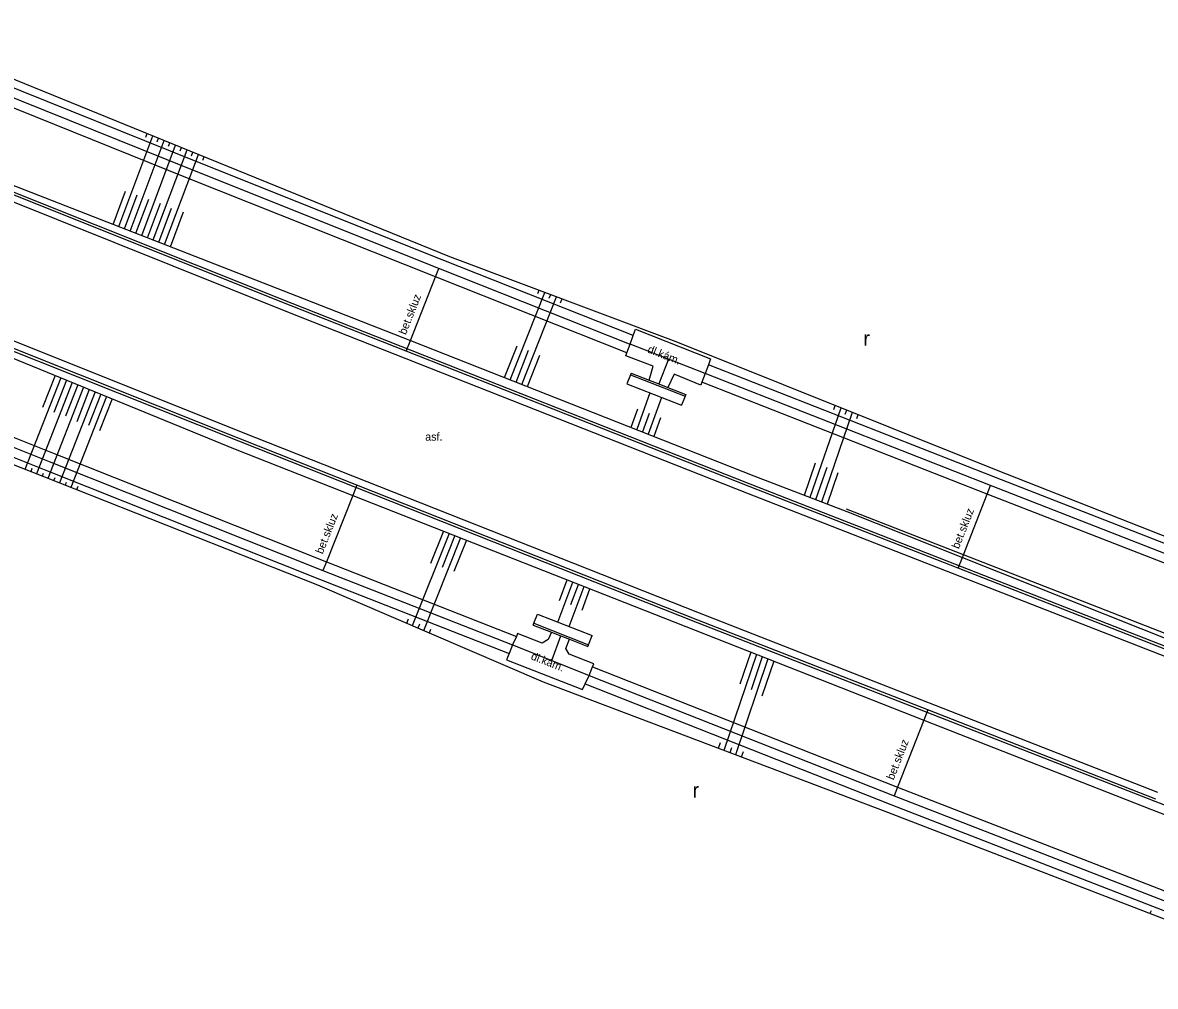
# Model space of a CAD drawing. Extents: x -541281 to -539153, y -1183881 to -1182141.
# Drawn here: x -539618 to -539526, y -1182393.9 to -1182315.6 of the extents above; entities that cross this region are included whole.
import ezdxf

# ---------------------------------------------------------------- set-up
doc = ezdxf.new("R2010")
doc.units = 0
for name, color, linetype in [('Vrstva 10', 7, 'Continuous'), ('Vrstva 11', 7, 'Continuous'), ('Vrstva 14', 7, 'Continuous'), ('Vrstva 15', 7, 'Continuous'), ('Vrstva 36', 7, 'Continuous'), ('Vrstva 40', 7, 'Continuous'), ('Vrstva 7', 7, 'Continuous'), ('Vrstva 9', 7, 'Continuous')]:
    doc.layers.add(name, color=color, linetype=linetype)

msp = doc.modelspace()

# ---------------------------------------------------------------- linework, layer by layer
at = {"layer": 'Vrstva 10'}
for p, q in [((-539633.427, -1182324.268), (-539596.388, -1182339.094)), ((-539600.28, -1182348.833), (-539637.384, -1182333.994)), ((-539596.388, -1182339.094), (-539559.233, -1182353.771)), ((-539563.059, -1182363.539), (-539600.28, -1182348.833)), ((-539559.233, -1182353.771), (-539521.885, -1182368.358)), ((-539525.827, -1182378.1), (-539563.059, -1182363.539))]:
    msp.add_line(p, q, dxfattribs=at)
at = {"layer": 'Vrstva 11'}
for p, q in [((-539604.094, -1182326.792), (-539630.271, -1182316.259)), ((-539604.652, -1182328.184), (-539630.831, -1182317.651)), ((-539596.224, -1182338.56), (-539633.235, -1182323.796)), ((-539583.961, -1182334.823), (-539604.094, -1182326.792)), ((-539584.515, -1182336.217), (-539604.652, -1182328.184)), ((-539600.45, -1182349.35), (-539637.358, -1182334.621)), ((-539568.449, -1182340.984), (-539583.961, -1182334.823)), ((-539568.956, -1182342.397), (-539584.515, -1182336.217)), ((-539639.779, -1182340.846), (-539615.478, -1182350.572)), ((-539568.264, -1182340.47), (-539562.157, -1182342.878)), ((-539640.341, -1182342.238), (-539616.034, -1182351.966)), ((-539566.839, -1182343.459), (-539569.035, -1182342.617)), ((-539567.157, -1182344.596), (-539566.839, -1182343.459)), ((-539539.148, -1182352.463), (-539562.338, -1182343.354)), ((-539568.668, -1182344.166), (-539564.239, -1182345.9)), ((-539565.113, -1182344.124), (-539565.638, -1182345.191)), ((-539562.967, -1182345.004), (-539565.113, -1182344.124)), ((-539539.696, -1182353.859), (-539562.872, -1182344.756)), ((-539568.959, -1182344.911), (-539564.53, -1182346.645)), ((-539615.478, -1182350.572), (-539593.375, -1182359.368)), ((-539616.034, -1182351.966), (-539593.927, -1182360.762)), ((-539515.774, -1182361.592), (-539539.148, -1182352.463)), ((-539516.318, -1182362.99), (-539539.696, -1182353.859)), ((-539593.375, -1182359.368), (-539577.943, -1182365.438)), ((-539593.927, -1182360.762), (-539578.528, -1182366.821)), ((-539576.22, -1182363.616), (-539571.792, -1182365.355)), ((-539576.512, -1182364.36), (-539572.084, -1182366.099)), ((-539575.853, -1182365.977), (-539577.837, -1182365.187)), ((-539575.355, -1182365.683), (-539575.853, -1182365.977)), ((-539575.08, -1182365.084), (-539575.355, -1182365.683)), ((-539573.92, -1182366.403), (-539573.631, -1182365.653)), ((-539573.649, -1182366.862), (-539573.92, -1182366.403)), ((-539571.636, -1182367.641), (-539573.649, -1182366.862)), ((-539578.739, -1182367.321), (-539572.562, -1182369.748)), ((-539571.751, -1182367.902), (-539546.971, -1182377.688)), ((-539572.355, -1182369.277), (-539547.519, -1182379.084)), ((-539546.971, -1182377.688), (-539522.336, -1182387.256)), ((-539547.519, -1182379.084), (-539522.88, -1182388.654))]:
    msp.add_line(p, q, dxfattribs=at)
for points in [[(-539559.033, -1182353.235), (-539586.891, -1182342.243), (-539596.224, -1182338.56)], [(-539569.035, -1182342.617), (-539568.956, -1182342.397), (-539568.702, -1182341.69), (-539568.449, -1182340.984), (-539568.264, -1182340.47)], [(-539562.157, -1182342.878), (-539562.338, -1182343.354), (-539562.605, -1182344.055), (-539562.872, -1182344.756), (-539562.967, -1182345.004)], [(-539568.613, -1182344.026), (-539568.668, -1182344.166), (-539568.959, -1182344.911)], [(-539568.613, -1182344.026), (-539567.157, -1182344.596), (-539566.363, -1182344.907), (-539565.638, -1182345.191), (-539564.184, -1182345.76)], [(-539564.184, -1182345.76), (-539564.239, -1182345.9), (-539564.53, -1182346.645)], [(-539563.193, -1182364.108), (-539590.904, -1182353.131), (-539600.45, -1182349.35)], [(-539521.662, -1182367.863), (-539542.053, -1182359.881), (-539559.033, -1182353.235)], [(-539576.567, -1182364.5), (-539576.512, -1182364.36), (-539576.22, -1182363.616)], [(-539525.991, -1182378.637), (-539544.517, -1182371.402), (-539563.193, -1182364.108)], [(-539576.567, -1182364.5), (-539575.08, -1182365.084), (-539574.331, -1182365.378), (-539573.631, -1182365.653), (-539572.139, -1182366.239)], [(-539577.837, -1182365.187), (-539577.943, -1182365.438), (-539578.255, -1182366.122), (-539578.528, -1182366.821), (-539578.739, -1182367.321)], [(-539572.139, -1182366.239), (-539572.084, -1182366.099), (-539571.792, -1182365.355)], [(-539572.562, -1182369.748), (-539572.355, -1182369.277), (-539572.031, -1182368.598), (-539571.751, -1182367.902), (-539571.636, -1182367.641)]]:
    msp.add_lwpolyline(points, dxfattribs=at)
at = {"layer": 'Vrstva 14'}
for p, q in [((-539630.009, -1182315.556), (-539603.743, -1182326.276)), ((-539604.373, -1182327.488), (-539630.551, -1182316.955)), ((-539633.049, -1182323.249), (-539595.808, -1182337.745)), ((-539603.743, -1182326.276), (-539583.363, -1182334.559)), ((-539584.238, -1182335.52), (-539604.373, -1182327.488)), ((-539583.363, -1182334.559), (-539564.975, -1182341.474)), ((-539637.577, -1182335.183), (-539600.773, -1182350.201)), ((-539584.515, -1182336.217), (-539584.238, -1182335.52)), ((-539568.747, -1182341.673), (-539584.238, -1182335.52)), ((-539586.553, -1182341.386), (-539584.515, -1182336.217)), ((-539640.06, -1182341.542), (-539615.756, -1182351.269)), ((-539586.891, -1182342.243), (-539586.553, -1182341.386)), ((-539568.702, -1182341.69), (-539568.747, -1182341.673)), ((-539565.579, -1182342.894), (-539568.702, -1182341.69)), ((-539564.975, -1182341.474), (-539538.976, -1182351.889)), ((-539616.254, -1182352.488), (-539640.7, -1182342.904)), ((-539565.579, -1182342.894), (-539566.363, -1182344.907)), ((-539562.605, -1182344.055), (-539565.579, -1182342.894)), ((-539562.59, -1182344.061), (-539562.605, -1182344.055)), ((-539539.422, -1182353.161), (-539562.59, -1182344.061)), ((-539615.756, -1182351.269), (-539593.651, -1182360.065)), ((-539538.976, -1182351.889), (-539515.654, -1182361.073)), ((-539594.083, -1182361.274), (-539616.254, -1182352.488)), ((-539558.645, -1182352.367), (-539551.084, -1182355.266)), ((-539590.904, -1182353.131), (-539591.233, -1182353.963)), ((-539516.046, -1182362.291), (-539539.422, -1182353.161)), ((-539542.053, -1182359.881), (-539541.708, -1182359.001)), ((-539541.708, -1182359.001), (-539541.625, -1182358.787)), ((-539593.651, -1182360.065), (-539578.255, -1182366.122)), ((-539575.749, -1182369.148), (-539594.083, -1182361.274)), ((-539575.063, -1182367.378), (-539574.331, -1182365.378)), ((-539578.255, -1182366.122), (-539575.063, -1182367.378)), ((-539575.063, -1182367.378), (-539572.031, -1182368.598)), ((-539572.031, -1182368.598), (-539547.245, -1182378.386)), ((-539547.775, -1182379.728), (-539575.749, -1182369.148)), ((-539544.517, -1182371.402), (-539544.842, -1182372.234)), ((-539544.842, -1182372.234), (-539546.971, -1182377.688)), ((-539546.971, -1182377.688), (-539547.245, -1182378.386)), ((-539547.245, -1182378.386), (-539522.608, -1182387.955)), ((-539523.159, -1182389.228), (-539547.775, -1182379.728))]:
    msp.add_line(p, q, dxfattribs=at)
for points in [[(-539595.808, -1182337.745), (-539586.553, -1182341.386), (-539558.645, -1182352.367)], [(-539600.773, -1182350.201), (-539591.233, -1182353.963), (-539563.423, -1182364.931)], [(-539591.233, -1182353.963), (-539593.375, -1182359.368), (-539593.651, -1182360.065)], [(-539541.625, -1182358.787), (-539539.696, -1182353.859), (-539539.422, -1182353.161)], [(-539551.084, -1182355.266), (-539541.708, -1182359.001), (-539521.503, -1182367.05)], [(-539563.423, -1182364.931), (-539544.842, -1182372.234), (-539526.355, -1182379.501)], [(-539526.355, -1182379.501), (-539498.228, -1182390.3), (-539488.959, -1182393.859)]]:
    msp.add_lwpolyline(points, dxfattribs=at)
at = {"layer": 'Vrstva 15'}
for p, q in [((-539610.243, -1182332.126), (-539607.473, -1182324.754)), ((-539609.311, -1182332.489), (-539606.547, -1182325.132)), ((-539608.05, -1182324.869), (-539607.936, -1182324.565)), ((-539607.118, -1182325.23), (-539607.01, -1182324.943)), ((-539606.19, -1182325.603), (-539606.084, -1182325.321)), ((-539608.379, -1182332.852), (-539605.62, -1182325.51)), ((-539607.447, -1182333.215), (-539604.694, -1182325.888)), ((-539606.515, -1182333.577), (-539603.768, -1182326.266)), ((-539605.261, -1182325.976), (-539605.157, -1182325.699)), ((-539604.343, -1182326.375), (-539604.231, -1182326.077)), ((-539603.405, -1182326.72), (-539603.305, -1182326.454)), ((-539610.709, -1182331.945), (-539609.695, -1182329.247)), ((-539609.777, -1182332.308), (-539608.736, -1182329.538)), ((-539608.845, -1182332.67), (-539607.805, -1182329.902)), ((-539607.913, -1182333.033), (-539606.857, -1182330.222)), ((-539606.981, -1182333.396), (-539605.944, -1182330.636)), ((-539606.049, -1182333.759), (-539604.981, -1182330.915)), ((-539576.197, -1182337.567), (-539576.089, -1182337.295)), ((-539578.435, -1182344.581), (-539575.62, -1182337.471)), ((-539577.504, -1182344.947), (-539574.684, -1182337.823)), ((-539575.267, -1182337.937), (-539575.152, -1182337.647)), ((-539574.347, -1182338.33), (-539574.216, -1182337.999)), ((-539578.9, -1182344.398), (-539577.875, -1182341.808)), ((-539577.969, -1182344.764), (-539576.943, -1182342.173)), ((-539577.039, -1182345.13), (-539576.032, -1182342.587)), ((-539614.95, -1182344.416), (-539617.859, -1182351.859)), ((-539615.412, -1182344.228), (-539616.429, -1182346.83)), ((-539614.486, -1182344.605), (-539615.511, -1182347.228)), ((-539614.023, -1182344.794), (-539616.927, -1182352.224)), ((-539613.098, -1182345.172), (-539615.997, -1182352.59)), ((-539612.172, -1182345.55), (-539615.067, -1182352.958)), ((-539613.561, -1182344.983), (-539614.56, -1182347.54)), ((-539612.634, -1182345.361), (-539613.66, -1182347.987)), ((-539567.085, -1182345.645), (-539568.165, -1182348.621)), ((-539611.245, -1182345.928), (-539614.137, -1182353.327)), ((-539611.709, -1182345.739), (-539612.703, -1182348.283)), ((-539610.782, -1182346.117), (-539611.802, -1182348.728)), ((-539566.153, -1182346.009), (-539567.234, -1182348.988)), ((-539568.091, -1182346.949), (-539568.631, -1182348.438)), ((-539567.163, -1182347.324), (-539567.7, -1182348.804)), ((-539554.067, -1182354.122), (-539551.567, -1182346.845)), ((-539553.133, -1182354.48), (-539550.638, -1182347.217)), ((-539552.14, -1182346.975), (-539552.032, -1182346.659)), ((-539551.22, -1182347.374), (-539551.102, -1182347.031)), ((-539550.284, -1182347.73), (-539550.172, -1182347.404)), ((-539566.219, -1182347.654), (-539566.769, -1182349.171)), ((-539617.293, -1182351.788), (-539617.392, -1182352.042)), ((-539554.534, -1182353.943), (-539553.633, -1182351.321)), ((-539553.6, -1182354.301), (-539552.699, -1182351.679)), ((-539552.665, -1182354.66), (-539551.787, -1182352.105)), ((-539616.38, -1182352.197), (-539616.462, -1182352.406)), ((-539615.435, -1182352.529), (-539615.531, -1182352.774)), ((-539614.513, -1182352.916), (-539614.602, -1182353.143)), ((-539613.567, -1182353.241), (-539613.672, -1182353.511)), ((-539583.398, -1182357.053), (-539586.407, -1182364.57)), ((-539582.468, -1182357.42), (-539585.488, -1182364.965)), ((-539583.863, -1182356.87), (-539584.919, -1182359.508)), ((-539582.933, -1182357.237), (-539583.965, -1182359.814)), ((-539582.003, -1182357.604), (-539583.022, -1182360.15)), ((-539574.57, -1182364.264), (-539573.359, -1182361.012)), ((-539574.448, -1182362.505), (-539573.824, -1182360.829)), ((-539573.504, -1182362.836), (-539572.894, -1182361.196)), ((-539573.638, -1182364.63), (-539572.428, -1182361.379)), ((-539572.608, -1182363.296), (-539571.963, -1182361.563)), ((-539586.729, -1182364.029), (-539586.867, -1182364.373)), ((-539585.813, -1182364.431), (-539585.948, -1182364.768)), ((-539584.908, -1182364.862), (-539585.029, -1182365.163)), ((-539558.896, -1182366.71), (-539559.779, -1182369.311)), ((-539558.43, -1182366.893), (-539561.078, -1182374.697)), ((-539557.499, -1182367.259), (-539560.143, -1182375.05)), ((-539557.965, -1182367.076), (-539558.879, -1182369.771)), ((-539557.033, -1182367.443), (-539557.997, -1182370.284)), ((-539561.39, -1182374.062), (-539561.546, -1182374.52)), ((-539560.475, -1182374.475), (-539560.61, -1182374.874)), ((-539559.527, -1182374.793), (-539559.674, -1182375.228)), ((-539526.379, -1182387.716), (-539526.466, -1182387.952))]:
    msp.add_line(p, q, dxfattribs=at)
at = {"layer": 'Vrstva 7'}
msp.add_lwpolyline([(-539521.267, -1182366.732), (-539541.625, -1182358.787), (-539551.132, -1182355.077)], dxfattribs=at)
at = {"layer": 'Vrstva 9'}
for p, q in [((-539596.15, -1182338.374), (-539633.161, -1182323.61)), ((-539637.432, -1182334.807), (-539600.524, -1182349.536)), ((-539558.96, -1182353.049), (-539596.151, -1182338.374)), ((-539600.524, -1182349.536), (-539563.266, -1182364.294)), ((-539521.589, -1182367.677), (-539558.96, -1182353.049)), ((-539563.266, -1182364.294), (-539526.063, -1182378.824)), ((-539526.063, -1182378.824), (-539488.675, -1182393.228))]:
    msp.add_line(p, q, dxfattribs=at)

# ---------------------------------------------------------------- texts
at = {"layer": 'Vrstva 36'}
for p in [(-539549.752, -1182341.812), (-539563.626, -1182378.517)]:
    msp.add_text('r', height=1.2, dxfattribs=at).set_placement(p)
at = {"layer": 'Vrstva 40'}
for s, rotation, p in [('bet.skluz', 68.46504, (-539586.923, -1182340.962)), ('dl.kám.', 338.4806, (-539567.346, -1182342.338)), ('bet.skluz', 68.38832, (-539593.68, -1182358.78)), ('bet.skluz', 68.61876, (-539541.995, -1182358.362)), ('dl.kám.', 338.54968, (-539576.812, -1182367.272)), ('bet.skluz', 68.66403, (-539547.293, -1182377.135))]:
    msp.add_text(s, height=0.65, rotation=rotation, dxfattribs=at).set_placement(p)
msp.add_text('asf.', height=0.65, dxfattribs=at).set_placement((-539585.344, -1182349.524))

doc.saveas('drawing.dxf')
